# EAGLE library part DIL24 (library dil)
SOCKET Dual In Line
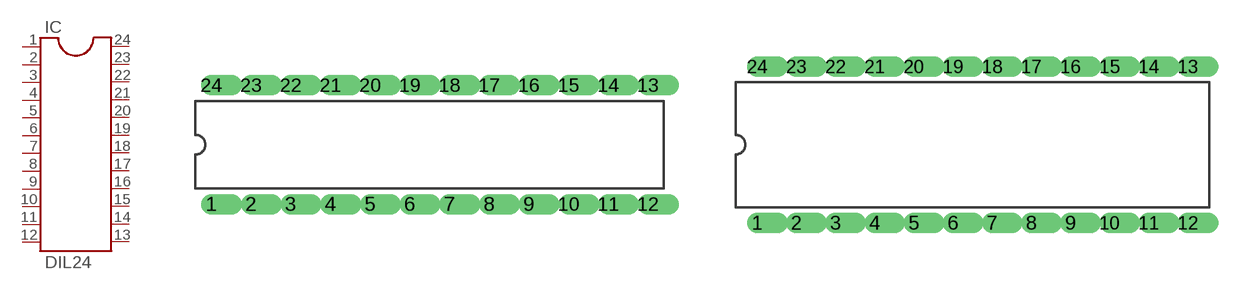
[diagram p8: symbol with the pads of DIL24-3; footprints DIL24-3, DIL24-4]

Designator prefix IC

## DIL24/3  [DIL24-3]
1  1  pas
2  2  pas
3  3  pas
4  4  pas
5  5  pas
6  6  pas
7  7  pas
8  8  pas
9  9  pas
10  10  pas
11  11  pas
12  12  pas
13  13  pas
14  14  pas
15  15  pas
16  16  pas
17  17  pas
18  18  pas
19  19  pas
20  20  pas
21  21  pas
22  22  pas
23  23  pas
24  24  pas

## DIL24/4  [DIL24-4]
Pads as for DIL24-3

## DIL24/6  [DIL24-6]
Pads as for DIL24-3

## DIL24/9  [DIL24-9]
Pads as for DIL24-3

## Footprint DIL24-3 (pad centres in mm)
SOCKET Dual In Line, 0.3 inch
drill 0.813 offset: 1 -13.97,-3.81; 2 -11.43,-3.81; 3 -8.89,-3.81; 4 -6.35,-3.81; 5 -3.81,-3.81; 6 -1.27,-3.81; 7 1.27,-3.81; 8 3.81,-3.81; 9 6.35,-3.81; 10 8.89,-3.81; 11 11.43,-3.81; 12 13.97,-3.81; 13 13.97,3.81; 14 11.43,3.81; 15 8.89,3.81; 16 6.35,3.81; 17 3.81,3.81; 18 1.27,3.81; 19 -1.27,3.81; 20 -3.81,3.81; 21 -6.35,3.81; 22 -8.89,3.81; 23 -11.43,3.81; 24 -13.97,3.81

## Footprint DIL24-4 (pad centres in mm)
SOCKET Dual In Line, 0.4 inch
drill 0.813 offset: 1 -13.97,-5.08; 2 -11.43,-5.08; 3 -8.89,-5.08; 4 -6.35,-5.08; 5 -3.81,-5.08; 6 -1.27,-5.08; 7 1.27,-5.08; 8 3.81,-5.08; 9 6.35,-5.08; 10 8.89,-5.08; 11 11.43,-5.08; 12 13.97,-5.08; 13 13.97,5.08; 14 11.43,5.08; 15 8.89,5.08; 16 6.35,5.08; 17 3.81,5.08; 18 1.27,5.08; 19 -1.27,5.08; 20 -3.81,5.08; 21 -6.35,5.08; 22 -8.89,5.08; 23 -11.43,5.08; 24 -13.97,5.08

## Footprint DIL24-6 (pad centres in mm)
SOCKET Dual In Line, 0.6 inch
drill 0.813 offset: 1 -13.97,-7.62; 2 -11.43,-7.62; 3 -8.89,-7.62; 4 -6.35,-7.62; 5 -3.81,-7.62; 6 -1.27,-7.62; 7 1.27,-7.62; 8 3.81,-7.62; 9 6.35,-7.62; 10 8.89,-7.62; 11 11.43,-7.62; 12 13.97,-7.62; 13 13.97,7.62; 14 11.43,7.62; 15 8.89,7.62; 16 6.35,7.62; 17 3.81,7.62; 18 1.27,7.62; 19 -1.27,7.62; 20 -3.81,7.62; 21 -6.35,7.62; 22 -8.89,7.62; 23 -11.43,7.62; 24 -13.97,7.62

## Footprint DIL24-9 (pad centres in mm)
SOCKET Dual In Line, 0.9 inch
drill 0.813 offset: 1 -13.97,-11.43; 2 -11.43,-11.43; 3 -8.89,-11.43; 4 -6.35,-11.43; 5 -3.81,-11.43; 6 -1.27,-11.43; 7 1.27,-11.43; 8 3.81,-11.43; 9 6.35,-11.43; 10 8.89,-11.43; 11 11.43,-11.43; 12 13.97,-11.43; 13 13.97,11.43; 14 11.43,11.43; 15 8.89,11.43; 16 6.35,11.43; 17 3.81,11.43; 18 1.27,11.43; 19 -1.27,11.43; 20 -3.81,11.43; 21 -6.35,11.43; 22 -8.89,11.43; 23 -11.43,11.43; 24 -13.97,11.43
